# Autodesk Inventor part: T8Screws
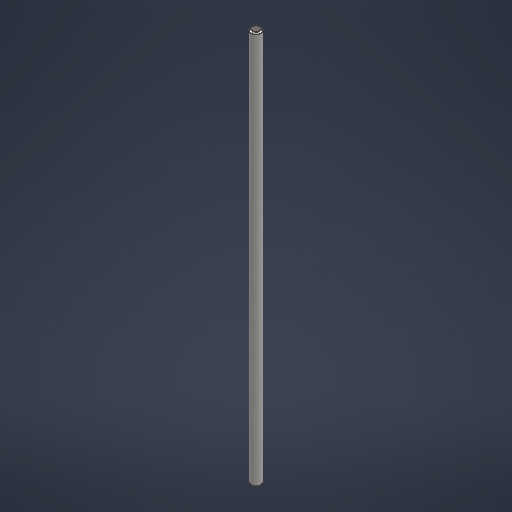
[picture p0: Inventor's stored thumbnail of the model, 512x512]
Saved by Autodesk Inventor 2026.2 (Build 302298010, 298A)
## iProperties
Created: 2026-04
Part Number: T8Screws
Material: 스테인리스스틸
Document SubType Name: Modeling
Designer: work
Density: 8 g/cm^3
Appearance: 반연마
Author: work
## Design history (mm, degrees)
sketch "스케치1"
  geometry: C1 r 4 at (0, 0); 1 further point
  constraints: 1 centre point, 1 coincident
  dimensions: "d0" = 8 diameter of C1
extrude "돌출1" new body sketch "스케치1" distance "d1" = 300; taper "d2" = 0 deg
chamfer "모따기1" distance "d3" = 1; stored, may be unused: second distance "d4" = 2, angle "d5" = 45 deg
feature "스레드1" dims "d6" = 298, "d7" = 0
node "솔리드1"
feature "A9D066F2-1C7D-4E18-AEED-F7BC21143FA4" dims "d6" = 298, "d7" = 0
